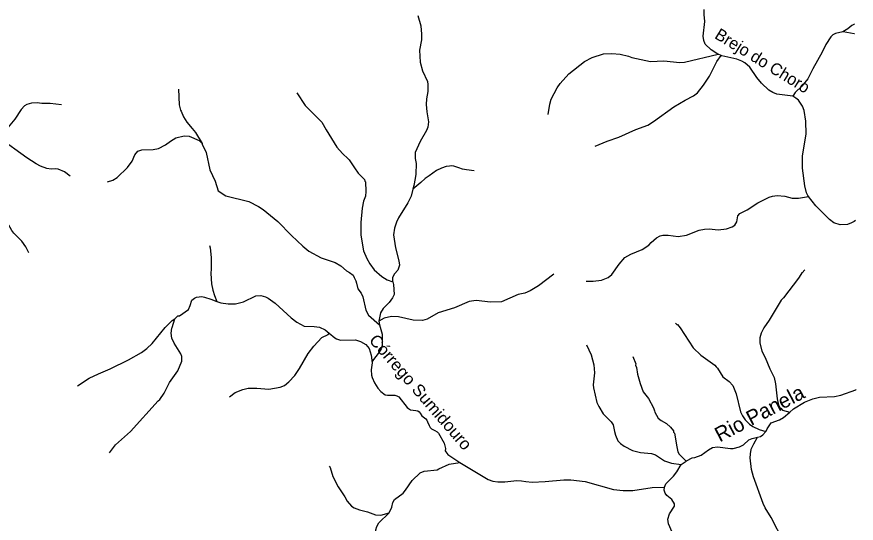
# Model space of a CAD drawing. Extents: x 280.4 to 335.6, y 8893.9 to 8949.5.
# Drawn here: x 324.16 to 335.41, y 8933.17 to 8939.96 of the extents above; entities that cross this region are included whole.
import ezdxf
from ezdxf.enums import TextEntityAlignment as Align

# ---------------------------------------------------------------- set-up
doc = ezdxf.new("R2010")
doc.units = 0
doc.header["$LTSCALE"] = 0.064
doc.layers.add('61', color=7, linetype='Continuous')
doc.layers.add('7', color=7, linetype='Continuous', lineweight=25)

msp = doc.modelspace()

# ---------------------------------------------------------------- linework, layer by layer
at = {"layer": '7'}
for p, q in [((333.597, 8939.4365), (333.556, 8939.4573)), ((329.0121, 8935.8776), (329.0241, 8935.8298)), ((333.0631, 8933.9551), (333.1269, 8934.0007))]:
    msp.add_line(p, q, dxfattribs=at)
for points in [[(329.5351, 8939.9752), (329.575, 8939.8369), (329.5855, 8939.7269), (329.5859, 8939.7232), (329.5843, 8939.6471), (329.5558, 8939.5121), (329.5655, 8939.3484), (329.5971, 8939.2345), (329.6636, 8939.0914), (329.6707, 8939.0508), (329.6693, 8938.9579), (329.6516, 8938.8589), (329.6454, 8938.7829), (329.6548, 8938.6837), (329.6802, 8938.5508), (329.6686, 8938.48), (329.6512, 8938.432), (329.5652, 8938.2855), (329.5014, 8938.1367), (329.4981, 8938.0575), (329.5139, 8937.9902), (329.5091, 8937.8483), (329.4986, 8937.7889), (329.482, 8937.6953), (329.4696, 8937.6448)], [(333.556, 8939.4573), (333.5411, 8939.4649), (333.4637, 8939.5158), (333.3839, 8939.5924), (333.3657, 8939.6411), (333.3587, 8939.6992), (333.3778, 8939.8927), (333.3715, 8939.988), (333.3721, 8940.0544)], [(335.385, 8939.8613), (335.3734, 8939.8544), (335.3497, 8939.8402), (335.2938, 8939.7969), (335.2291, 8939.7548)], [(335.2291, 8939.7548), (335.1282, 8939.733), (335.0923, 8939.7151), (335.0648, 8939.6908), (334.9982, 8939.5864), (334.9523, 8939.4817), (334.8242, 8939.2616), (334.7575, 8939.1277), (334.6803, 8939.0284), (334.5869, 8938.9428), (334.5567, 8938.8934)], [(335.3856, 8939.7284), (335.3786, 8939.7296), (335.2306, 8939.7551), (335.2291, 8939.7548)], [(331.2804, 8938.646), (331.3018, 8938.7862), (331.3215, 8938.8538), (331.3993, 8939.0061), (331.4432, 8939.0649), (331.559, 8939.1934), (331.7689, 8939.3586), (331.8688, 8939.4131), (332.0217, 8939.4609), (332.1336, 8939.4673), (332.2455, 8939.4545), (332.3551, 8939.4279), (332.4005, 8939.411), (332.6524, 8939.357), (332.8315, 8939.365), (333.0458, 8939.3427), (333.1077, 8939.3504), (333.556, 8939.4573)], [(331.9106, 8938.2227), (332.0722, 8938.2901), (332.2285, 8938.3461), (332.456, 8938.4467), (332.6177, 8938.5069), (332.6896, 8938.5522), (332.9652, 8938.7508), (333.1156, 8938.8404), (333.2272, 8938.8959), (333.279, 8938.9386), (333.3608, 8939.0405), (333.4401, 8939.1597), (333.5397, 8939.3593), (333.597, 8939.4365)], [(334.5567, 8938.8934), (334.3445, 8938.9203), (334.2897, 8938.9405), (334.2341, 8938.9727), (334.1362, 8939.0675), (334.0747, 8939.1418), (333.9822, 8939.2818), (333.9135, 8939.3426), (333.8739, 8939.3645), (333.8057, 8939.389), (333.6056, 8939.4321), (333.597, 8939.4365)], [(326.3317, 8938.9881), (326.3399, 8938.7794), (326.3556, 8938.7068), (326.3666, 8938.6931), (326.3988, 8938.6166), (326.4409, 8938.546), (326.5136, 8938.4599), (326.5569, 8938.4086), (326.648, 8938.2574)], [(327.9157, 8938.94), (328.0252, 8938.7669), (328.251, 8938.5471), (328.3066, 8938.4439), (328.4485, 8938.211), (328.5261, 8938.1268), (328.6035, 8938.0542), (328.6142, 8938.039), (328.6889, 8937.9322), (328.7371, 8937.8633), (328.8202, 8937.7773), (328.8255, 8937.752), (328.8328, 8937.745), (328.8406, 8937.6169), (328.8342, 8937.5515), (328.8073, 8937.4874), (328.788, 8937.3915), (328.772, 8937.2013), (328.7722, 8937.0309), (328.8092, 8936.8205), (328.8516, 8936.7173), (328.894, 8936.6456), (328.9527, 8936.5664), (329.0549, 8936.4742), (329.1239, 8936.4304), (329.1998, 8936.4027)], [(334.7666, 8937.55), (334.7577, 8937.5614), (334.7385, 8937.5992), (334.7182, 8937.6914), (334.686, 8937.929), (334.6893, 8938.0944), (334.734, 8938.3838), (334.7307, 8938.5573), (334.7084, 8938.6997), (334.6856, 8938.7579), (334.6317, 8938.8403), (334.6, 8938.8688), (334.5567, 8938.8934)], [(324.7653, 8938.777), (324.6132, 8938.7972), (324.5019, 8938.7957), (324.4379, 8938.8051), (324.3637, 8938.8003), (324.2998, 8938.7824), (324.2675, 8938.7627), (324.2232, 8938.7151), (324.1373, 8938.5846), (324.0472, 8938.4785), (323.9198, 8938.3687), (323.8651, 8938.3368)], [(324.3247, 8936.7933), (324.2839, 8936.8741), (324.2316, 8936.9501), (324.123, 8937.0588), (324.0994, 8937.0913), (324.0374, 8937.2065), (323.9741, 8937.2603), (323.8223, 8937.3458), (323.7861, 8937.3561), (323.6088, 8937.3468), (323.5223, 8937.3626), (323.4581, 8937.4067), (323.2859, 8937.5679), (323.238, 8937.6015), (323.0515, 8937.7322), (322.9671, 8937.8387), (322.9325, 8937.9103), (322.8823, 8937.9794), (322.7308, 8938.1293), (322.6665, 8938.2375), (322.6008, 8938.3979)], [(324.8814, 8937.8231), (324.8032, 8937.88), (324.7177, 8937.9141), (324.6843, 8937.9191), (324.6259, 8937.9161), (324.5684, 8937.9258), (324.4834, 8937.9542), (324.4232, 8937.9849), (324.2982, 8938.0651), (323.9242, 8938.3332), (323.9035, 8938.3428), (323.8651, 8938.3368)], [(325.3776, 8937.7451), (325.4501, 8937.7696), (325.5068, 8937.803), (325.6481, 8937.9364), (325.7093, 8938.0217), (325.7446, 8938.1063), (325.7864, 8938.1582), (325.8397, 8938.1736), (325.9932, 8938.1781), (326.0614, 8938.1923), (326.1577, 8938.2411), (326.223, 8938.2916), (326.2954, 8938.333), (326.4068, 8938.3635), (326.4736, 8938.3554), (326.6076, 8938.2977), (326.648, 8938.2574)], [(326.648, 8938.2574), (326.6469, 8938.2489), (326.7024, 8938.1367), (326.7508, 8937.9057), (326.8205, 8937.7536), (326.8603, 8937.6246), (326.9656, 8937.556), (327.2725, 8937.4807), (327.4037, 8937.4147), (327.4631, 8937.3744), (327.5607, 8937.2943), (327.661, 8937.2119), (327.8427, 8937.0254), (327.9953, 8936.8824), (328.0756, 8936.8178), (328.2395, 8936.7271), (328.4297, 8936.6638), (328.5064, 8936.619), (328.5795, 8936.5525), (328.6209, 8936.5299), (328.6689, 8936.4929), (328.6844, 8936.4632), (328.7041, 8936.4193), (328.7146, 8936.3854), (328.7315, 8936.3102), (328.775, 8936.2544), (328.7974, 8936.2048), (328.8369, 8936.0242), (328.8765, 8935.96), (329.0241, 8935.8298)], [(330.2917, 8937.891), (330.1875, 8937.9041), (330.1322, 8937.9171), (330.085, 8937.935), (330.0443, 8937.948), (330.0166, 8937.9562), (329.9856, 8937.9578), (329.958, 8937.9562), (329.914, 8937.9496), (329.8521, 8937.9285), (329.7854, 8937.8959), (329.6893, 8937.8259), (329.6323, 8937.7917), (329.5737, 8937.7364), (329.4696, 8937.6448)], [(329.4696, 8937.6448), (329.447, 8937.5521), (329.4012, 8937.4636), (329.2786, 8937.2629), (329.2499, 8937.2053), (329.2219, 8937.1224), (329.2103, 8937.0348), (329.2357, 8936.8613), (329.2789, 8936.6878), (329.2881, 8936.6275), (329.2662, 8936.559), (329.2225, 8936.5097), (329.1945, 8936.4635), (329.196, 8936.4153), (329.1998, 8936.4027)], [(331.7908, 8936.4157), (331.8856, 8936.4141), (331.9968, 8936.4268), (332.0862, 8936.4643), (332.1358, 8936.5028), (332.23, 8936.642), (332.308, 8936.7294), (332.3863, 8936.7774), (332.5384, 8936.8376), (332.6282, 8936.8962), (332.6593, 8936.9319), (332.7339, 8936.9953), (332.7798, 8937.0203), (332.8181, 8937.0284), (332.8859, 8937.0315), (333.0211, 8937.0142), (333.1322, 8937.0318), (333.3052, 8937.0954), (333.3739, 8937.1104), (333.4386, 8937.1132), (333.5584, 8937.1021), (333.6713, 8937.1155), (333.745, 8937.1403), (333.7817, 8937.1655), (333.8057, 8937.2102), (333.8206, 8937.2883), (333.8491, 8937.3221), (333.9461, 8937.3679), (334.0896, 8937.4633), (334.2399, 8937.5386), (334.2855, 8937.5536), (334.3494, 8937.5626), (334.4525, 8937.5514), (334.5486, 8937.5259), (334.6302, 8937.5273), (334.6355, 8937.5282), (334.7666, 8937.55)], [(335.3965, 8937.2285), (335.3771, 8937.2155), (335.3443, 8937.1935), (335.2881, 8937.1712), (335.1915, 8937.1677), (335.1076, 8937.1953), (335.0478, 8937.2391), (334.8663, 8937.4223), (334.7666, 8937.55)], [(326.7434, 8936.893), (326.7543, 8936.8592), (326.7665, 8936.7294), (326.7697, 8936.5783), (326.7634, 8936.5176), (326.7715, 8936.3792), (326.7881, 8936.2917), (326.8142, 8936.2236), (326.8454, 8936.1422)], [(331.3553, 8936.5074), (331.1528, 8936.3497), (331.0385, 8936.2826), (330.9685, 8936.2538), (330.8787, 8936.2352), (330.657, 8936.1373), (330.5087, 8936.1314), (330.3176, 8936.1535), (330.2225, 8936.1427), (330.0274, 8936.0556), (329.8057, 8935.9876), (329.6611, 8935.9027), (329.5987, 8935.8885), (329.4721, 8935.8895), (329.278, 8935.936), (329.1821, 8935.9393), (329.0861, 8935.9157), (329.0121, 8935.8776)], [(334.7192, 8936.5657), (334.6841, 8936.5262), (334.6778, 8936.5269), (334.6424, 8936.4666), (334.6334, 8936.4546), (334.4337, 8936.1894), (334.4031, 8936.1568), (334.2398, 8935.893), (334.1675, 8935.7883), (334.1324, 8935.7179), (334.1163, 8935.6518), (334.1141, 8935.5864), (334.1436, 8935.4763), (334.1873, 8935.3917), (334.2499, 8935.2383), (334.3087, 8935.123), (334.3274, 8935.039), (334.3473, 8934.8344), (334.3667, 8934.7522), (334.3896, 8934.7123), (334.399, 8934.7101), (334.4214, 8934.6855), (334.5172, 8934.6581)], [(329.1998, 8936.4027), (329.21, 8936.3695), (329.2197, 8936.2344), (329.1953, 8936.1882), (329.1498, 8936.1256), (329.0702, 8936.0451), (329.0375, 8935.9873), (329.0121, 8935.8776)], [(326.2823, 8935.909), (326.3229, 8935.9492), (326.3415, 8935.951), (326.462, 8936.0349), (326.4878, 8936.089), (326.5093, 8936.1598), (326.5427, 8936.1871), (326.5706, 8936.1981), (326.6447, 8936.2075), (326.6776, 8936.2013), (326.7646, 8936.1707), (326.8454, 8936.1422)], [(326.8454, 8936.1422), (326.8953, 8936.1246), (326.9967, 8936.109), (327.0952, 8936.109), (327.1999, 8936.1355), (327.3647, 8936.2191), (327.4342, 8936.2209), (327.4973, 8936.2022), (327.5324, 8936.1847), (327.6269, 8936.1201), (327.8386, 8935.9213), (327.9154, 8935.8638), (328.0127, 8935.8111), (328.145, 8935.8066), (328.2194, 8935.7951), (328.2953, 8935.7633), (328.3501, 8935.7168)], [(324.9767, 8935.0106), (325.1329, 8935.1114), (325.2575, 8935.172), (325.4161, 8935.2372), (325.6604, 8935.3592), (325.8357, 8935.4581), (325.9064, 8935.5096), (325.9764, 8935.578), (326.1529, 8935.7944), (326.2471, 8935.8855), (326.2823, 8935.909)], [(325.4044, 8934.1142), (325.4887, 8934.2217), (325.6866, 8934.3973), (326.0601, 8934.8072), (326.0792, 8934.8281), (326.139, 8934.912), (326.2116, 8935.0534), (326.3199, 8935.2127), (326.3728, 8935.3405), (326.3746, 8935.4045), (326.3633, 8935.4404), (326.2711, 8935.5805), (326.2425, 8935.6499), (326.2339, 8935.7164), (326.2425, 8935.7842), (326.2434, 8935.7915), (326.2823, 8935.909)], [(329.0241, 8935.8298), (329.0565, 8935.7011), (329.0564, 8935.5516), (329.0437, 8935.505), (329.0197, 8935.4596), (328.9284, 8935.3456), (328.9243, 8935.317)], [(332.9871, 8935.852), (333.0039, 8935.8339), (333.0109, 8935.834), (333.0466, 8935.7901), (333.2207, 8935.5207), (333.3254, 8935.4234), (333.5111, 8935.2894), (333.5327, 8935.2651), (333.5503, 8935.2453), (333.6219, 8935.1323), (333.7068, 8935.0669), (333.7531, 8935.0171), (333.7979, 8934.9013), (333.8579, 8934.6628), (333.8825, 8934.6071), (333.9185, 8934.5555), (333.9762, 8934.4959), (334.0205, 8934.4657), (334.1046, 8934.4246), (334.1954, 8934.3982)], [(327.0144, 8934.8647), (327.087, 8934.9201), (327.1927, 8934.963), (327.2622, 8934.9814), (327.3806, 8934.9814), (327.541, 8934.9671), (327.6908, 8934.9911), (327.7516, 8935.0167), (327.8097, 8935.0634), (327.8891, 8935.1483), (327.9515, 8935.2421), (328.0663, 8935.443), (328.1408, 8935.5434), (328.2501, 8935.6574), (328.3363, 8935.6994), (328.3501, 8935.7168)], [(328.3501, 8935.7168), (328.4233, 8935.6548), (328.4477, 8935.6403), (328.4994, 8935.6246), (328.6991, 8935.6289), (328.768, 8935.6054), (328.8376, 8935.5643), (328.8617, 8935.5358), (328.8841, 8935.5093), (328.9096, 8935.4237), (328.9243, 8935.317)], [(331.7928, 8935.5596), (331.8555, 8935.4269), (331.8921, 8935.2932), (331.9002, 8935.1867), (331.8842, 8935.0246), (331.887, 8934.9835), (331.9336, 8934.7893), (331.9593, 8934.7316), (332.0168, 8934.6345), (332.1236, 8934.5277), (332.1535, 8934.487), (332.1714, 8934.3967), (332.1808, 8934.3489), (332.2157, 8934.2723), (332.2483, 8934.2383), (332.2973, 8934.2006), (332.4096, 8934.1421), (332.5168, 8934.1181), (332.6629, 8934.1029), (332.7195, 8934.0854), (332.8373, 8934.0068), (332.9325, 8933.9741), (333.0631, 8933.9551)], [(332.4166, 8935.4048), (332.4531, 8935.3047), (332.4503, 8935.2893), (332.4661, 8935.258), (332.4793, 8935.1687), (332.5111, 8935.0439), (332.5513, 8934.9287), (332.6225, 8934.8397), (332.6919, 8934.7168), (332.7046, 8934.6763), (332.7106, 8934.6573), (332.7547, 8934.5782), (332.7922, 8934.5474), (332.8666, 8934.5043), (332.9214, 8934.4557), (332.9585, 8934.4053), (332.9608, 8934.3885), (332.9715, 8934.3752), (333.0023, 8934.1914), (333.0187, 8934.1275), (333.0335, 8934.0958), (333.1269, 8934.0007)], [(328.9243, 8935.317), (328.9113, 8935.2269), (328.9144, 8935.1557), (328.9224, 8935.1206), (328.9535, 8935.0487), (328.9988, 8934.9799), (329.0391, 8934.9367), (329.0997, 8934.8899), (329.131, 8934.8839), (329.2293, 8934.8836), (329.2564, 8934.8774), (329.2824, 8934.8619), (329.3932, 8934.7204), (329.4103, 8934.7048), (329.4352, 8934.6908), (329.5098, 8934.6815), (329.5374, 8934.6733), (329.5518, 8934.6613), (329.5652, 8934.6454), (329.5898, 8934.6084), (329.6077, 8934.5929), (329.6404, 8934.5696), (329.6548, 8934.5521), (329.6652, 8934.5292), (329.6865, 8934.4784), (329.7025, 8934.453), (329.7198, 8934.4336), (329.7635, 8934.4119), (329.7927, 8934.3939), (329.8108, 8934.3757), (329.8884, 8934.2409), (329.9039, 8934.1722), (329.9032, 8934.1381), (329.9119, 8934.1252), (329.9356, 8934.0901), (330.0993, 8933.9823)], [(334.5172, 8934.6581), (334.5677, 8934.7029), (334.7132, 8934.7895), (334.8268, 8934.8359), (334.9147, 8934.8585), (335.1153, 8934.8695), (335.2016, 8934.884), (335.401, 8934.9575), (335.4064, 8934.9595)], [(334.1954, 8934.3982), (334.1992, 8934.4028), (334.2126, 8934.4334), (334.2663, 8934.5131), (334.3796, 8934.5563), (334.4335, 8934.584), (334.5172, 8934.6581)], [(334.0822, 8934.3205), (334.1234, 8934.331), (334.1576, 8934.3528), (334.1954, 8934.3982)], [(333.1269, 8934.0007), (333.1344, 8934.0061), (333.2081, 8934.0444), (333.2442, 8934.0477), (333.3305, 8934.083), (333.4272, 8934.1539), (333.4801, 8934.1818), (333.5471, 8934.1946), (333.7225, 8934.1707), (333.7568, 8934.171), (333.8443, 8934.1926), (333.8947, 8934.2193), (333.9673, 8934.285), (334.0131, 8934.3029), (334.0822, 8934.3205)], [(334.4339, 8932.9251), (334.2666, 8933.2469), (334.1871, 8933.3742), (334.1602, 8933.4336), (334.0307, 8933.7892), (334.0062, 8933.8867), (333.9856, 8934.0451), (333.9936, 8934.1409), (334.0011, 8934.1469), (334.0017, 8934.1603), (334.0339, 8934.2352), (334.0822, 8934.3205)], [(328.3501, 8933.9339), (328.3617, 8933.9162), (328.3983, 8933.7949), (328.4686, 8933.6551), (328.5562, 8933.5234), (328.5893, 8933.4628), (328.6485, 8933.3957), (328.6847, 8933.3739), (328.7552, 8933.3472), (328.8599, 8933.3235), (328.967, 8933.2815), (329.0391, 8933.2785), (329.1521, 8933.3059)], [(329.1521, 8933.3059), (329.1851, 8933.3829), (329.2006, 8933.4445), (329.222, 8933.4863), (329.3393, 8933.5722), (329.3721, 8933.6115), (329.4592, 8933.7414), (329.5651, 8933.8449), (329.6211, 8933.8654), (329.795, 8933.8852), (329.8178, 8933.8958), (329.956, 8933.9604), (330.0993, 8933.9823)], [(330.0993, 8933.9823), (330.4775, 8933.7531), (330.5408, 8933.7325), (330.6047, 8933.7229), (330.7014, 8933.7229), (330.8614, 8933.742), (330.9238, 8933.7388), (330.9814, 8933.7262), (331.0669, 8933.7181), (331.2419, 8933.7261), (331.4904, 8933.7518), (331.5851, 8933.7515), (331.7746, 8933.7294), (332.1564, 8933.6195), (332.2864, 8933.6077), (332.4158, 8933.6077), (332.6726, 8933.6462), (332.8392, 8933.6526)], [(332.8392, 8933.6526), (332.8569, 8933.6946), (332.9577, 8933.7985), (333.0048, 8933.8597), (333.0631, 8933.9551)], [(332.973, 8932.9142), (332.9718, 8932.9793), (332.8936, 8933.1591), (332.8837, 8933.2238), (332.9062, 8933.294), (332.9744, 8933.398), (332.9717, 8933.4277), (332.9352, 8933.4887), (332.8705, 8933.5426), (332.8464, 8933.5711), (332.8344, 8933.6141), (332.8392, 8933.6526)], [(328.9721, 8933.0589), (328.9716, 8933.0781), (328.9867, 8933.1252), (329.0151, 8933.1726), (329.1521, 8933.3059)]]:
    msp.add_lwpolyline(points, dxfattribs=at)

# ---------------------------------------------------------------- texts
at = {"layer": '61'}
for s, height, rotation, p in [('Brejo do Choro', 0.16, 328.392, (334.1106, 8939.3004)), ('Rio Panela', 0.2, 27.646, (334.1578, 8934.5541))]:
    msp.add_text(s, height=height, rotation=rotation, dxfattribs=at).set_placement(p, align=Align.CENTER)
at = {"layer": '61', "width": 1.05}
msp.add_text('Córrego Sumidouro', height=0.16, rotation=310.815, dxfattribs=at).set_placement((329.5124, 8934.8743), align=Align.CENTER)

doc.saveas('drawing.dxf')
